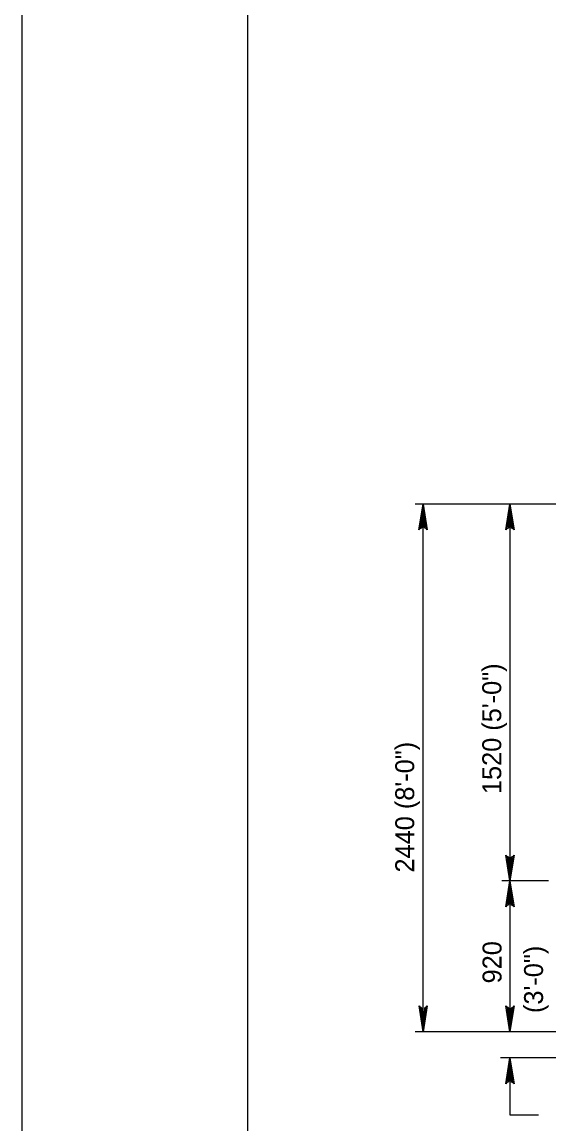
# Model space of a CAD drawing. Extents: x -4 to 901, y -468 to 720.
# Drawn here: x -3.7 to 89.7, y -370.2 to -174.7 of the extents above; entities that cross this region are included whole.
import ezdxf

# ---------------------------------------------------------------- set-up
doc = ezdxf.new("R2010")
doc.units = 0
for name, color, linetype in [('1', 7, 'Continuous'), ('2', 7, 'Continuous'), ('3', 7, 'Continuous'), ('PLT-BNDY', 7, 'Continuous')]:
    doc.layers.add(name, color=color, linetype=linetype)

msp = doc.modelspace()

# ---------------------------------------------------------------- linework, layer by layer
at = {"layer": '1'}
msp.add_lwpolyline([(822.258, -452.972125), (822.258, 111.027875), (36.258, 111.027875), (36.258, -452.972125), (822.258, -452.972125), (822.258, -426.613125), (622.258, -426.613125), (622.258, -361.935625), (822.258, -361.935625), (822.258, -332.972125), (622.258, -332.972125), (622.258, -452.972125), (701.0595, -452.972125), (701.0595, -426.613125), (701.0595, -452.972125), (778.0595, -452.972125), (778.0595, -426.613125), (778.0595, -438.929625), (822.258, -438.929625)], dxfattribs=at)
at = {"layer": '2'}
for p, q in [((109.33575, -260.207625), (65.93175, -260.207625)), ((67.37175, -353.807625), (67.37175, -260.207625)), ((82.76575, -260.207625), (82.76575, -327.061625)), ((89.60575, -327.061625), (81.32575, -327.061625)), ((82.76575, -327.061625), (82.76575, -353.807625)), ((118.93575, -353.807625), (65.93175, -353.807625)), ((113.65575, -358.443625), (81.08575, -358.443625))]:
    msp.add_line(p, q, dxfattribs=at)
for points in [[(66.82575, -264.567625), (67.14175, -264.405625), (67.37175, -260.207625), (66.82575, -264.567625), (66.63375, -264.791625), (67.37175, -260.207625), (67.57975, -264.401625), (67.89175, -264.555625), (67.37175, -260.207625), (68.09975, -264.791625), (67.89175, -264.555625)], [(82.21975, -264.567625), (82.53575, -264.405625), (82.76575, -260.207625), (82.21975, -264.567625), (82.02775, -264.791625), (82.76575, -260.207625), (82.97375, -264.401625), (83.28575, -264.555625), (82.76575, -260.207625), (83.49375, -264.791625), (83.28575, -264.555625)], [(83.31375, -322.703625), (82.99775, -322.865625), (82.76575, -327.061625), (83.31375, -322.703625), (83.50575, -322.479625), (82.76575, -327.061625), (82.55975, -322.867625), (82.24775, -322.715625), (82.76575, -327.061625), (82.03775, -322.479625), (82.24775, -322.715625)], [(82.21975, -331.421625), (82.53575, -331.257625), (82.76575, -327.061625), (82.21975, -331.421625), (82.02775, -331.643625), (82.76575, -327.061625), (82.97375, -331.255625), (83.28575, -331.407625), (82.76575, -327.061625), (83.49375, -331.643625), (83.28575, -331.407625)], [(67.91975, -349.449625), (67.60375, -349.611625), (67.37175, -353.807625), (67.91975, -349.449625), (68.11175, -349.225625), (67.37175, -353.807625), (67.16575, -349.615625), (66.85375, -349.461625), (67.37175, -353.807625), (66.64375, -349.225625), (66.85375, -349.461625)], [(83.31375, -349.449625), (82.99775, -349.611625), (82.76575, -353.807625), (83.31375, -349.449625), (83.50575, -349.225625), (82.76575, -353.807625), (82.55975, -349.615625), (82.24775, -349.461625), (82.76575, -353.807625), (82.03775, -349.225625), (82.24775, -349.461625)], [(82.21975, -362.801625), (82.53575, -362.639625), (82.76575, -358.443625), (82.21975, -362.801625), (82.02775, -363.025625), (82.76575, -358.443625), (82.97375, -362.635625), (83.28575, -362.789625), (82.76575, -358.443625), (83.49375, -363.025625), (83.28575, -362.789625)], [(82.76575, -358.443625), (82.76575, -368.523625), (87.80575, -368.523625)]]:
    msp.add_lwpolyline(points, dxfattribs=at)
at = {"layer": 'PLT-BNDY'}
msp.add_lwpolyline([(-3.742, 126.027875), (837.258, 126.027875), (837.258, -467.972125), (-3.742, -467.972125)], close=True, dxfattribs=at)

# ---------------------------------------------------------------- texts
at = {"layer": '3'}
for s, p in [('1520 (5\'-0")', (81.21675, -311.657125)), ('2440 (8\'-0")', (65.787, -325.571125)), ('920', (81.2685, -345.235375)), ('(3\'-0")', (88.62375, -350.487625))]:
    msp.add_text(s, height=3.36, rotation=90, dxfattribs=at).set_placement(p)

doc.saveas('drawing.dxf')
